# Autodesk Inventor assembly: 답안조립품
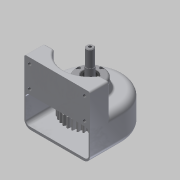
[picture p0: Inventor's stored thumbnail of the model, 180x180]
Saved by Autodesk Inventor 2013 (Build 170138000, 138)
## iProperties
Created: 2015-02
Part Number: 답안조립품
Document SubType Name: Assembly
Designer: Administrator
Author: Administrator
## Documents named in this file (9)
- C:\Users\Administrator\Desktop\450216V1005\답안조립품.iam
- C:\Users\Administrator\Desktop\450216V1005\본체.ipt
- C:\Users\Administrator\Desktop\450216V1005\베어링 6001.ipt
- C:\Users\Administrator\Desktop\450216V1005\축.ipt
- C:\Users\Administrator\Desktop\450216V1005\키4x4.ipt
- C:\Users\Administrator\Desktop\450216V1005\키5x5.ipt
- C:\Users\Administrator\Desktop\450216V1005\스퍼기어.ipt
- C:\Users\Administrator\Desktop\450216V1005\오일실.ipt
- C:\Users\Administrator\Desktop\450216V1005\축커버.ipt
